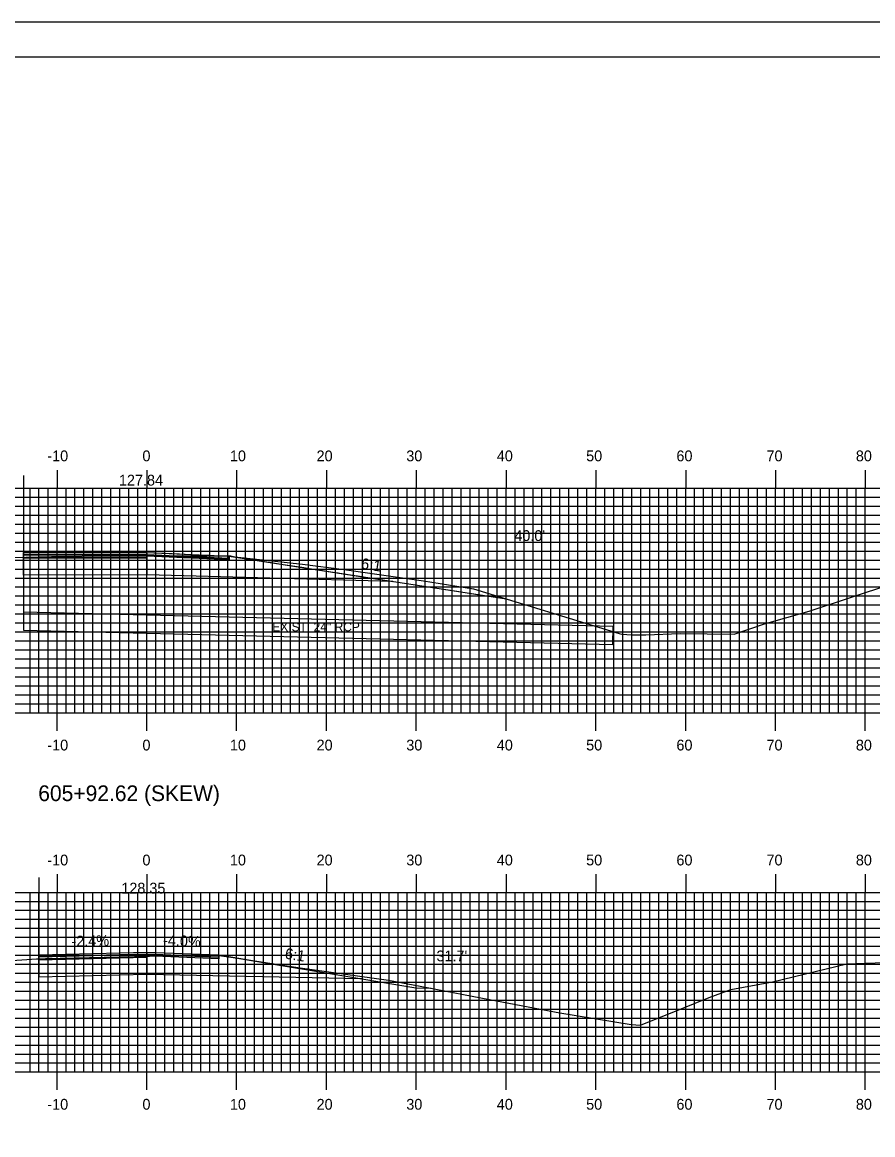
# Model space of a CAD drawing. Extents: x 842175 to 842518, y 363538 to 363758.
# Drawn here: x 842327 to 842421.7, y 363633.7 to 363757.6 of the extents above; entities that cross this region are included whole.
import ezdxf

# ---------------------------------------------------------------- set-up
doc = ezdxf.new("R2010")
doc.units = 0
for name, color, linetype in [('ANNOTATION', 7, 'Continuous'), ('BORDER', 7, 'Continuous'), ('D_Drainage_Culvert', 7, 'Continuous'), ('D_Roadway_Centerline', 7, 'Continuous'), ('D_Roadway_Centerline_Text', 7, 'Continuous'), ('D_Roadway_Edge_Shoulder', 7, 'Continuous'), ('D_Roadway_Edge_TW', 7, 'Continuous'), ('D_Roadway_FinishedGrade', 7, 'Continuous'), ('D_Roadway_Pavement', 7, 'Continuous'), ('D_Roadway_SlopeLines', 7, 'Continuous'), ('D_Roadway_SubGrade', 7, 'Continuous'), ('D_Text_Monospaced', 7, 'Continuous'), ('D_Text_Standard', 7, 'Continuous'), ('H_V ANNOTATION', 7, 'Continuous'), ('M_Roadway_Centerline', 7, 'Continuous'), ('MAJOR', 7, 'Continuous'), ('MINOR', 7, 'Continuous'), ('PLOT BOUNDARY', 7, 'Continuous'), ('S_Roadway_Centerline', 7, 'Continuous')]:
    doc.layers.add(name, color=color, linetype=linetype)

msp = doc.modelspace()

# ---------------------------------------------------------------- linework, layer by layer
at = {"layer": 'BORDER'}
msp.add_lwpolyline([(842191.29, 363543.72), (842511.29, 363543.72), (842511.29, 363753.72), (842191.29, 363753.72)], close=True, dxfattribs=at)
at = {"layer": 'D_Drainage_Culvert'}
msp.add_lwpolyline([(842327.15, 363689.9), (842392.77, 363688.33), (842392.82, 363690.33), (842327.15, 363691.9)], dxfattribs=at)
at = {"layer": 'D_Roadway_Centerline'}
for points in [[(842327.15, 363698.55), (842327.27, 363698.55), (842327.29, 363698.55), (842328.13, 363698.55), (842328.2, 363698.55), (842328.29, 363698.55), (842329.34, 363698.56), (842330.84, 363698.56), (842331.39, 363698.56), (842332.62, 363698.56), (842333.44, 363698.56), (842334.41, 363698.57), (842335.49, 363698.56), (842336.19, 363698.57), (842337.55, 363698.56), (842337.98, 363698.56), (842339.6, 363698.56), (842340.88, 363698.56), (842341.66, 363698.52), (842341.88, 363698.51), (842343.71, 363698.44), (842344.54, 363698.4), (842345.77, 363698.35), (842346.55, 363698.32), (842347.83, 363698.26), (842348.24, 363698.24), (842349.89, 363698.17), (842350.04, 363698.16), (842351.76, 363697.89), (842351.95, 363697.86), (842352.2, 363697.83), (842354.01, 363697.55), (842354.52, 363697.47), (842356.08, 363697.23), (842356.85, 363697.11), (842358.14, 363696.91), (842359.17, 363696.75), (842360.21, 363696.59), (842360.89, 363696.49), (842361.9, 363696.33), (842362.15, 363696.29), (842362.27, 363696.27), (842362.53, 363696.23), (842363.07, 363696.15), (842364.05, 363696), (842364.34, 363695.95), (842366.17, 363695.67), (842366.41, 363695.64), (842366.6, 363695.61), (842368.29, 363695.35)], [(842373.17, 363694.59), (842374.7, 363694.36), (842375.62, 363694.21), (842376.77, 363694.04), (842378.18, 363693.82), (842378.84, 363693.72), (842380.92, 363693.4)], [(842328.88, 363653.78), (842340.88, 363654.07), (842348.89, 363653.75), (842351.2, 363653.36), (842364.84, 363651.09)]]:
    msp.add_lwpolyline(points, dxfattribs=at)
at = {"layer": 'D_Roadway_Edge_Shoulder'}
for points in [[(842340.88, 363698.56), (842350.04, 363698.16), (842350.04, 363697.91), (842340.88, 363698.31)], [(842340.88, 363654.07), (842348.89, 363653.75), (842348.89, 363653.5), (842340.88, 363653.82)]]:
    msp.add_lwpolyline(points, close=True, dxfattribs=at)
at = {"layer": 'D_Roadway_Edge_TW'}
for points in [[(842327.15, 363698.55), (842340.88, 363698.56), (842340.88, 363698.31), (842327.15, 363698.3)], [(842328.88, 363653.78), (842340.88, 363654.07), (842340.88, 363653.82), (842328.88, 363653.53)]]:
    msp.add_lwpolyline(points, close=True, dxfattribs=at)
for points in [[(842327.15, 363698.55), (842327.15, 363698.3)], [(842328.88, 363653.78), (842328.88, 363653.53)]]:
    msp.add_lwpolyline(points, dxfattribs=at)
at = {"layer": 'D_Roadway_FinishedGrade'}
msp.add_lwpolyline([(842364.84, 363651.09), (842370.84, 363650.09), (842372.56, 363650.06)], dxfattribs=at)
at = {"layer": 'D_Roadway_Pavement'}
for points in [[(842327.15, 363698.3), (842340.88, 363698.31), (842340.88, 363697.97), (842327.15, 363697.97)], [(842340.88, 363698.31), (842350.04, 363697.91), (842350.04, 363697.74), (842340.88, 363698.14)], [(842328.88, 363653.53), (842340.88, 363653.82), (842340.88, 363653.49), (842328.88, 363653.2)], [(842340.88, 363653.82), (842348.89, 363653.5), (842348.89, 363653.33), (842340.88, 363653.65)]]:
    msp.add_lwpolyline(points, close=True, dxfattribs=at)
for points in [[(842327.15, 363698.3), (842327.15, 363697.97)], [(842340.88, 363698.31), (842340.88, 363697.97)], [(842340.88, 363698.31), (842340.88, 363697.97)], [(842328.88, 363653.53), (842328.88, 363653.2)], [(842340.88, 363653.82), (842340.88, 363653.49)], [(842340.88, 363653.82), (842340.88, 363653.49)]]:
    msp.add_lwpolyline(points, dxfattribs=at)
at = {"layer": 'D_Roadway_SlopeLines'}
for points in [[(842350.04, 363698.16), (842380.92, 363693.4)], [(842348.89, 363653.75), (842351.2, 363653.36)]]:
    msp.add_lwpolyline(points, dxfattribs=at)
at = {"layer": 'D_Roadway_SubGrade'}
for p, q in [((842327.15, 363707.15), (842327.15, 363696.05)), ((842327.15, 363696.05), (842327.15, 363689.9)), ((842328.88, 363662.38), (842328.88, 363651.28))]:
    msp.add_line(p, q, dxfattribs=at)
for points in [[(842340.88, 363697.97), (842340.88, 363698.31), (842350.04, 363697.91), (842350.04, 363698.16), (842368.29, 363695.35), (842340.88, 363696.06)], [(842327.15, 363697.97), (842340.88, 363697.97), (842340.88, 363696.06), (842327.15, 363696.05)], [(842328.88, 363653.2), (842340.88, 363653.49), (842340.88, 363651.57), (842328.88, 363651.28)], [(842340.88, 363653.49), (842340.88, 363653.82), (842348.89, 363653.5), (842348.89, 363653.75), (842364.84, 363651.09), (842340.88, 363651.57)]]:
    msp.add_lwpolyline(points, close=True, dxfattribs=at)
for points in [[(842327.15, 363697.97), (842327.15, 363696.05)], [(842328.88, 363653.2), (842328.88, 363651.28)]]:
    msp.add_lwpolyline(points, dxfattribs=at)
at = {"layer": 'MAJOR'}
for p, q in [((842330.89, 363707.73), (842330.89, 363705.72)), ((842340.88, 363707.73), (842340.88, 363705.72)), ((842350.89, 363707.73), (842350.89, 363705.72)), ((842360.89, 363707.73), (842360.89, 363705.72)), ((842370.89, 363707.73), (842370.89, 363705.72)), ((842380.89, 363707.73), (842380.89, 363705.72)), ((842390.89, 363707.73), (842390.89, 363705.72)), ((842400.89, 363707.73), (842400.89, 363705.72)), ((842410.89, 363707.73), (842410.89, 363705.72)), ((842420.89, 363707.73), (842420.89, 363705.72)), ((842200.89, 363705.72), (842480.89, 363705.72)), ((842200.89, 363705.72), (842480.89, 363705.72)), ((842330.89, 363680.72), (842330.89, 363705.72)), ((842340.88, 363680.72), (842340.88, 363705.72)), ((842350.89, 363680.72), (842350.89, 363705.72)), ((842360.89, 363680.72), (842360.89, 363705.72)), ((842370.89, 363680.72), (842370.89, 363705.72)), ((842380.89, 363680.72), (842380.89, 363705.72)), ((842390.89, 363680.72), (842390.89, 363705.72)), ((842400.89, 363680.72), (842400.89, 363705.72)), ((842410.89, 363680.72), (842410.89, 363705.72)), ((842420.89, 363680.72), (842420.89, 363705.72)), ((842200.89, 363700.72), (842480.89, 363700.72)), ((842200.89, 363695.72), (842480.89, 363695.72)), ((842200.89, 363690.72), (842480.89, 363690.72)), ((842200.89, 363685.72), (842480.89, 363685.72)), ((842200.89, 363680.72), (842480.89, 363680.72)), ((842200.89, 363680.72), (842480.89, 363680.72)), ((842330.89, 363678.72), (842330.89, 363680.72)), ((842340.88, 363678.72), (842340.88, 363680.72)), ((842350.89, 363678.72), (842350.89, 363680.72)), ((842360.89, 363678.72), (842360.89, 363680.72)), ((842370.89, 363678.72), (842370.89, 363680.72)), ((842380.89, 363678.72), (842380.89, 363680.72)), ((842390.89, 363678.72), (842390.89, 363680.72)), ((842400.89, 363678.72), (842400.89, 363680.72)), ((842410.89, 363678.72), (842410.89, 363680.72)), ((842420.89, 363678.72), (842420.89, 363680.72)), ((842330.89, 363662.73), (842330.89, 363660.72)), ((842340.88, 363662.73), (842340.88, 363660.72)), ((842350.89, 363662.73), (842350.89, 363660.72)), ((842360.89, 363662.73), (842360.89, 363660.72)), ((842370.89, 363662.73), (842370.89, 363660.72)), ((842380.89, 363662.73), (842380.89, 363660.72)), ((842390.89, 363662.73), (842390.89, 363660.72)), ((842400.89, 363662.73), (842400.89, 363660.72)), ((842410.89, 363662.73), (842410.89, 363660.72)), ((842420.89, 363662.73), (842420.89, 363660.72)), ((842200.89, 363660.72), (842480.89, 363660.72)), ((842200.89, 363660.72), (842480.89, 363660.72)), ((842330.89, 363640.72), (842330.89, 363660.72)), ((842340.88, 363640.72), (842340.88, 363660.72)), ((842350.89, 363640.72), (842350.89, 363660.72)), ((842360.89, 363640.72), (842360.89, 363660.72)), ((842370.89, 363640.72), (842370.89, 363660.72)), ((842380.89, 363640.72), (842380.89, 363660.72)), ((842390.89, 363640.72), (842390.89, 363660.72)), ((842400.89, 363640.72), (842400.89, 363660.72)), ((842410.89, 363640.72), (842410.89, 363660.72)), ((842420.89, 363640.72), (842420.89, 363660.72)), ((842200.89, 363655.72), (842480.89, 363655.72)), ((842200.89, 363650.72), (842480.89, 363650.72)), ((842200.89, 363645.72), (842480.89, 363645.72)), ((842200.89, 363640.72), (842480.89, 363640.72)), ((842200.89, 363640.72), (842480.89, 363640.72)), ((842330.89, 363638.72), (842330.89, 363640.72)), ((842340.88, 363638.72), (842340.88, 363640.72)), ((842350.89, 363638.72), (842350.89, 363640.72)), ((842360.89, 363638.72), (842360.89, 363640.72)), ((842370.89, 363638.72), (842370.89, 363640.72)), ((842380.89, 363638.72), (842380.89, 363640.72)), ((842390.89, 363638.72), (842390.89, 363640.72)), ((842400.89, 363638.72), (842400.89, 363640.72)), ((842410.89, 363638.72), (842410.89, 363640.72)), ((842420.89, 363638.72), (842420.89, 363640.72))]:
    msp.add_line(p, q, dxfattribs=at)
at = {"layer": 'MINOR'}
for p, q in [((842327.89, 363680.72), (842327.89, 363705.72)), ((842328.88, 363680.72), (842328.88, 363705.72)), ((842329.89, 363680.72), (842329.89, 363705.72)), ((842331.89, 363680.72), (842331.89, 363705.72)), ((842332.89, 363680.72), (842332.89, 363705.72)), ((842333.89, 363680.72), (842333.89, 363705.72)), ((842334.89, 363680.72), (842334.89, 363705.72)), ((842335.89, 363680.72), (842335.89, 363705.72)), ((842336.89, 363680.72), (842336.89, 363705.72)), ((842337.89, 363680.72), (842337.89, 363705.72)), ((842338.89, 363680.72), (842338.89, 363705.72)), ((842339.89, 363680.72), (842339.89, 363705.72)), ((842341.89, 363680.72), (842341.89, 363705.72)), ((842342.89, 363680.72), (842342.89, 363705.72)), ((842343.89, 363680.72), (842343.89, 363705.72)), ((842344.89, 363680.72), (842344.89, 363705.72)), ((842345.89, 363680.72), (842345.89, 363705.72)), ((842346.89, 363680.72), (842346.89, 363705.72)), ((842347.89, 363680.72), (842347.89, 363705.72)), ((842348.89, 363680.72), (842348.89, 363705.72)), ((842349.89, 363680.72), (842349.89, 363705.72)), ((842351.89, 363680.72), (842351.89, 363705.72)), ((842352.89, 363680.72), (842352.89, 363705.72)), ((842353.89, 363680.72), (842353.89, 363705.72)), ((842354.89, 363680.72), (842354.89, 363705.72)), ((842355.89, 363680.72), (842355.89, 363705.72)), ((842356.89, 363680.72), (842356.89, 363705.72)), ((842357.89, 363680.72), (842357.89, 363705.72)), ((842358.89, 363680.72), (842358.89, 363705.72)), ((842359.89, 363680.72), (842359.89, 363705.72)), ((842361.89, 363680.72), (842361.89, 363705.72)), ((842362.89, 363680.72), (842362.89, 363705.72)), ((842363.89, 363680.72), (842363.89, 363705.72)), ((842364.89, 363680.72), (842364.89, 363705.72)), ((842365.89, 363680.72), (842365.89, 363705.72)), ((842366.89, 363680.72), (842366.89, 363705.72)), ((842367.89, 363680.72), (842367.89, 363705.72)), ((842368.89, 363680.72), (842368.89, 363705.72)), ((842369.89, 363680.72), (842369.89, 363705.72)), ((842371.89, 363680.72), (842371.89, 363705.72)), ((842372.89, 363680.72), (842372.89, 363705.72)), ((842373.89, 363680.72), (842373.89, 363705.72)), ((842374.89, 363680.72), (842374.89, 363705.72)), ((842375.89, 363680.72), (842375.89, 363705.72)), ((842376.89, 363680.72), (842376.89, 363705.72)), ((842377.89, 363680.72), (842377.89, 363705.72)), ((842378.89, 363680.72), (842378.89, 363705.72)), ((842379.89, 363680.72), (842379.89, 363705.72)), ((842381.89, 363680.72), (842381.89, 363705.72)), ((842382.89, 363680.72), (842382.89, 363705.72)), ((842383.89, 363680.72), (842383.89, 363705.72)), ((842384.89, 363680.72), (842384.89, 363705.72)), ((842385.89, 363680.72), (842385.89, 363705.72)), ((842386.89, 363680.72), (842386.89, 363705.72)), ((842387.89, 363680.72), (842387.89, 363705.72)), ((842388.89, 363680.72), (842388.89, 363705.72)), ((842389.89, 363680.72), (842389.89, 363705.72)), ((842391.89, 363680.72), (842391.89, 363705.72)), ((842392.89, 363680.72), (842392.89, 363705.72)), ((842393.89, 363680.72), (842393.89, 363705.72)), ((842394.89, 363680.72), (842394.89, 363705.72)), ((842395.89, 363680.72), (842395.89, 363705.72)), ((842396.89, 363680.72), (842396.89, 363705.72)), ((842397.89, 363680.72), (842397.89, 363705.72)), ((842398.89, 363680.72), (842398.89, 363705.72)), ((842399.89, 363680.72), (842399.89, 363705.72)), ((842401.89, 363680.72), (842401.89, 363705.72)), ((842402.89, 363680.72), (842402.89, 363705.72)), ((842403.89, 363680.72), (842403.89, 363705.72)), ((842404.89, 363680.72), (842404.89, 363705.72)), ((842405.89, 363680.72), (842405.89, 363705.72)), ((842406.89, 363680.72), (842406.89, 363705.72)), ((842407.89, 363680.72), (842407.89, 363705.72)), ((842408.89, 363680.72), (842408.89, 363705.72)), ((842409.89, 363680.72), (842409.89, 363705.72)), ((842411.89, 363680.72), (842411.89, 363705.72)), ((842412.89, 363680.72), (842412.89, 363705.72)), ((842413.89, 363680.72), (842413.89, 363705.72)), ((842414.89, 363680.72), (842414.89, 363705.72)), ((842415.89, 363680.72), (842415.89, 363705.72)), ((842416.89, 363680.72), (842416.89, 363705.72)), ((842417.89, 363680.72), (842417.89, 363705.72)), ((842418.89, 363680.72), (842418.89, 363705.72)), ((842419.89, 363680.72), (842419.89, 363705.72)), ((842200.89, 363704.72), (842480.89, 363704.72)), ((842200.89, 363703.72), (842480.89, 363703.72)), ((842200.89, 363702.72), (842480.89, 363702.72)), ((842200.89, 363701.72), (842480.89, 363701.72)), ((842200.89, 363699.72), (842480.89, 363699.72)), ((842200.89, 363698.72), (842480.89, 363698.72)), ((842200.89, 363697.72), (842480.89, 363697.72)), ((842200.89, 363696.72), (842480.89, 363696.72)), ((842200.89, 363694.72), (842480.89, 363694.72)), ((842200.89, 363693.72), (842480.89, 363693.72)), ((842200.89, 363692.72), (842480.89, 363692.72)), ((842200.89, 363691.72), (842480.89, 363691.72)), ((842200.89, 363689.72), (842480.89, 363689.72)), ((842200.89, 363688.72), (842480.89, 363688.72)), ((842200.89, 363687.72), (842480.89, 363687.72)), ((842200.89, 363686.72), (842480.89, 363686.72)), ((842200.89, 363684.72), (842480.89, 363684.72)), ((842200.89, 363683.72), (842480.89, 363683.72)), ((842200.89, 363682.72), (842480.89, 363682.72)), ((842200.89, 363681.72), (842480.89, 363681.72)), ((842200.89, 363659.72), (842480.89, 363659.72)), ((842327.89, 363640.72), (842327.89, 363660.72)), ((842328.88, 363640.72), (842328.88, 363660.72)), ((842329.89, 363640.72), (842329.89, 363660.72)), ((842331.89, 363640.72), (842331.89, 363660.72)), ((842332.89, 363640.72), (842332.89, 363660.72)), ((842333.89, 363640.72), (842333.89, 363660.72)), ((842334.89, 363640.72), (842334.89, 363660.72)), ((842335.89, 363640.72), (842335.89, 363660.72)), ((842336.89, 363640.72), (842336.89, 363660.72)), ((842337.89, 363640.72), (842337.89, 363660.72)), ((842338.89, 363640.72), (842338.89, 363660.72)), ((842339.89, 363640.72), (842339.89, 363660.72)), ((842341.89, 363640.72), (842341.89, 363660.72)), ((842342.89, 363640.72), (842342.89, 363660.72)), ((842343.89, 363640.72), (842343.89, 363660.72)), ((842344.89, 363640.72), (842344.89, 363660.72)), ((842345.89, 363640.72), (842345.89, 363660.72)), ((842346.89, 363640.72), (842346.89, 363660.72)), ((842347.89, 363640.72), (842347.89, 363660.72)), ((842348.89, 363640.72), (842348.89, 363660.72)), ((842349.89, 363640.72), (842349.89, 363660.72)), ((842351.89, 363640.72), (842351.89, 363660.72)), ((842352.89, 363640.72), (842352.89, 363660.72)), ((842353.89, 363640.72), (842353.89, 363660.72)), ((842354.89, 363640.72), (842354.89, 363660.72)), ((842355.89, 363640.72), (842355.89, 363660.72)), ((842356.89, 363640.72), (842356.89, 363660.72)), ((842357.89, 363640.72), (842357.89, 363660.72)), ((842358.89, 363640.72), (842358.89, 363660.72)), ((842359.89, 363640.72), (842359.89, 363660.72)), ((842361.89, 363640.72), (842361.89, 363660.72)), ((842362.89, 363640.72), (842362.89, 363660.72)), ((842363.89, 363640.72), (842363.89, 363660.72)), ((842364.89, 363640.72), (842364.89, 363660.72)), ((842365.89, 363640.72), (842365.89, 363660.72)), ((842366.89, 363640.72), (842366.89, 363660.72)), ((842367.89, 363640.72), (842367.89, 363660.72)), ((842368.89, 363640.72), (842368.89, 363660.72)), ((842369.89, 363640.72), (842369.89, 363660.72)), ((842371.89, 363640.72), (842371.89, 363660.72)), ((842372.89, 363640.72), (842372.89, 363660.72)), ((842373.89, 363640.72), (842373.89, 363660.72)), ((842374.89, 363640.72), (842374.89, 363660.72)), ((842375.89, 363640.72), (842375.89, 363660.72)), ((842376.89, 363640.72), (842376.89, 363660.72)), ((842377.89, 363640.72), (842377.89, 363660.72)), ((842378.89, 363640.72), (842378.89, 363660.72)), ((842379.89, 363640.72), (842379.89, 363660.72)), ((842381.89, 363640.72), (842381.89, 363660.72)), ((842382.89, 363640.72), (842382.89, 363660.72)), ((842383.89, 363640.72), (842383.89, 363660.72)), ((842384.89, 363640.72), (842384.89, 363660.72)), ((842385.89, 363640.72), (842385.89, 363660.72)), ((842386.89, 363640.72), (842386.89, 363660.72)), ((842387.89, 363640.72), (842387.89, 363660.72)), ((842388.89, 363640.72), (842388.89, 363660.72)), ((842389.89, 363640.72), (842389.89, 363660.72)), ((842391.89, 363640.72), (842391.89, 363660.72)), ((842392.89, 363640.72), (842392.89, 363660.72)), ((842393.89, 363640.72), (842393.89, 363660.72)), ((842394.89, 363640.72), (842394.89, 363660.72)), ((842395.89, 363640.72), (842395.89, 363660.72)), ((842396.89, 363640.72), (842396.89, 363660.72)), ((842397.89, 363640.72), (842397.89, 363660.72)), ((842398.89, 363640.72), (842398.89, 363660.72)), ((842399.89, 363640.72), (842399.89, 363660.72)), ((842401.89, 363640.72), (842401.89, 363660.72)), ((842402.89, 363640.72), (842402.89, 363660.72)), ((842403.89, 363640.72), (842403.89, 363660.72)), ((842404.89, 363640.72), (842404.89, 363660.72)), ((842405.89, 363640.72), (842405.89, 363660.72)), ((842406.89, 363640.72), (842406.89, 363660.72)), ((842407.89, 363640.72), (842407.89, 363660.72)), ((842408.89, 363640.72), (842408.89, 363660.72)), ((842409.89, 363640.72), (842409.89, 363660.72)), ((842411.89, 363640.72), (842411.89, 363660.72)), ((842412.89, 363640.72), (842412.89, 363660.72)), ((842413.89, 363640.72), (842413.89, 363660.72)), ((842414.89, 363640.72), (842414.89, 363660.72)), ((842415.89, 363640.72), (842415.89, 363660.72)), ((842416.89, 363640.72), (842416.89, 363660.72)), ((842417.89, 363640.72), (842417.89, 363660.72)), ((842418.89, 363640.72), (842418.89, 363660.72)), ((842419.89, 363640.72), (842419.89, 363660.72)), ((842200.89, 363658.72), (842480.89, 363658.72)), ((842200.89, 363657.72), (842480.89, 363657.72)), ((842200.89, 363656.72), (842480.89, 363656.72)), ((842200.89, 363654.72), (842480.89, 363654.72)), ((842200.89, 363653.72), (842480.89, 363653.72)), ((842200.89, 363652.72), (842480.89, 363652.72)), ((842200.89, 363651.72), (842480.89, 363651.72)), ((842200.89, 363649.72), (842480.89, 363649.72)), ((842200.89, 363648.72), (842480.89, 363648.72)), ((842200.89, 363647.72), (842480.89, 363647.72)), ((842200.89, 363646.72), (842480.89, 363646.72)), ((842200.89, 363644.72), (842480.89, 363644.72)), ((842200.89, 363643.72), (842480.89, 363643.72)), ((842200.89, 363642.72), (842480.89, 363642.72)), ((842200.89, 363641.72), (842480.89, 363641.72))]:
    msp.add_line(p, q, dxfattribs=at)
at = {"layer": 'PLOT BOUNDARY'}
msp.add_lwpolyline([(842175.1, 363537.6), (842515.1, 363537.6), (842515.1, 363757.6), (842175.1, 363757.6)], close=True, dxfattribs=at)
at = {"layer": 'S_Roadway_Centerline'}
for points in [[(842326.18, 363698), (842327.4, 363698.05), (842330.28, 363698.11), (842337.1, 363698.19), (842350.26, 363698.18), (842350.7, 363698.09), (842358.22, 363697.25), (842362.85, 363696.65), (842371.71, 363695.41), (842377.25, 363694.52), (842393.48, 363689.54), (842393.78, 363689.48), (842394.91, 363689.4), (842396.44, 363689.38), (842400.28, 363689.56), (842406.28, 363689.45), (842409.66, 363690.63), (842414.63, 363692.04), (842423.86, 363695.09)], [(842322.55, 363652.91), (842328.59, 363653.3), (842329.05, 363653.33), (842329.11, 363653.33), (842329.6, 363653.35), (842336.13, 363653.49), (842344.57, 363653.69), (842346.65, 363653.75), (842347.13, 363653.74), (842348.93, 363653.68), (842350.5, 363653.47), (842357.7, 363652.37), (842367.8, 363650.93), (842372.11, 363650.14), (842379.03, 363648.8), (842386.86, 363647.3), (842394.83, 363646.02), (842395.85, 363645.92), (842400.2, 363647.69), (842403.51, 363649.03), (842405.92, 363649.9), (842410.54, 363650.77), (842418.83, 363652.76), (842423.03, 363652.9)]]:
    msp.add_lwpolyline(points, dxfattribs=at)

# ---------------------------------------------------------------- texts
at = {"layer": 'ANNOTATION'}
for s, rotation, p in [('6:1', 351.2278, (842364.69, 363696.77)), ('-2.4%', 1.3688, (842332.51, 363654.67)), ('-4.0%', 357.7094, (842342.68, 363654.8)), ('6:1', 350.5375, (842356.2, 363653.36))]:
    msp.add_text(s, height=1.2, rotation=rotation, dxfattribs=at).set_placement(p)
at = {"layer": 'D_Roadway_Centerline_Text'}
for s, p in [('127.84', (842337.78, 363706.02)), ('128.35', (842338.05, 363660.59))]:
    msp.add_text(s, height=1.2, dxfattribs=at).set_placement(p)
at = {"layer": 'D_Text_Monospaced'}
msp.add_text('EXIST. 24" RCP', height=1, dxfattribs=at).set_placement((842354.85, 363689.78))
at = {"layer": 'D_Text_Standard'}
for s, p in [("40.0'", (842381.81, 363699.84)), ("31.7'", (842373.14, 363653.04))]:
    msp.add_text(s, height=1.2, dxfattribs=at).set_placement(p)
at = {"layer": 'H_V ANNOTATION'}
for s, height, p in [('-10', 1.2, (842329.81, 363708.72)), ('0', 1.2, (842340.4, 363708.72)), ('10', 1.2, (842350.14, 363708.72)), ('20', 1.2, (842359.79, 363708.72)), ('30', 1.2, (842369.78, 363708.72)), ('40', 1.2, (842379.86, 363708.72)), ('50', 1.2, (842389.81, 363708.72)), ('60', 1.2, (842399.86, 363708.72)), ('70', 1.2, (842409.89, 363708.72)), ('80', 1.2, (842419.84, 363708.72)), ('-10', 1.2, (842329.81, 363676.52)), ('0', 1.2, (842340.4, 363676.52)), ('10', 1.2, (842350.14, 363676.52)), ('20', 1.2, (842359.79, 363676.52)), ('30', 1.2, (842369.78, 363676.52)), ('40', 1.2, (842379.86, 363676.52)), ('50', 1.2, (842389.81, 363676.52)), ('60', 1.2, (842399.86, 363676.52)), ('70', 1.2, (842409.89, 363676.52)), ('80', 1.2, (842419.84, 363676.52)), ('605+92.62 (SKEW)', 1.75, (842328.8, 363670.88)), ('-10', 1.2, (842329.81, 363663.72)), ('0', 1.2, (842340.4, 363663.72)), ('10', 1.2, (842350.14, 363663.72)), ('20', 1.2, (842359.79, 363663.72)), ('30', 1.2, (842369.78, 363663.72)), ('40', 1.2, (842379.86, 363663.72)), ('50', 1.2, (842389.81, 363663.72)), ('60', 1.2, (842399.86, 363663.72)), ('70', 1.2, (842409.89, 363663.72)), ('80', 1.2, (842419.84, 363663.72)), ('-10', 1.2, (842329.81, 363636.52)), ('0', 1.2, (842340.4, 363636.52)), ('10', 1.2, (842350.14, 363636.52)), ('20', 1.2, (842359.79, 363636.52)), ('30', 1.2, (842369.78, 363636.52)), ('40', 1.2, (842379.86, 363636.52)), ('50', 1.2, (842389.81, 363636.52)), ('60', 1.2, (842399.86, 363636.52)), ('70', 1.2, (842409.89, 363636.52)), ('80', 1.2, (842419.84, 363636.52))]:
    msp.add_text(s, height=height, dxfattribs=at).set_placement(p)
at = {"layer": 'M_Roadway_Centerline'}
for s, p in [('C', (842329.04, 363653.33)), ('L', (842329.05, 363653.32))]:
    msp.add_text(s, height=0.0146, dxfattribs=at).set_placement(p)

doc.saveas('drawing.dxf')
